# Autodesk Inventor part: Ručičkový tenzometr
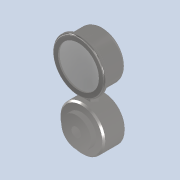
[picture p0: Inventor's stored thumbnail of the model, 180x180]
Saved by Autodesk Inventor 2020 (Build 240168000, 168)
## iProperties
Created: 2025-03
Part Number: Ručičkový tenzometr
Material: Hliník 6061
Document SubType Name: Modeling
Designer: doma
Density: 2.7 g/cm^3
Appearance: Hliník – plochý
Mass: 508.275 g
Surface Area: 271.618 cm^2
Volume: 188.25 cm^3
Author: doma
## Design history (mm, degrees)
sketch "Náčrt1"
  geometry: C1 r 30 at (0, 0); 1 further point
  constraints: 1 centre point, 1 coincident
  dimensions: "d0" = 60 diameter of C1
extrude "Vysunutí1" new body sketch "Náčrt1" stored distance "d1" = 30; taper "d2" = 0 deg
chamfer "Zkosení1" distance "d3" = 2; stored, may be unused: second distance "d4" = 2, angle "d5" = 45 deg
sketch "Náčrt2"
  geometry: C1 r 20 at (0, 0); 1 further point
  constraints: 1 centre point, 1 coincident
  dimensions: "d6" = 40 diameter of C1
extrude "Vysunutí2" join sketch "Náčrt2" distance "d7" = 7; taper "d8" = 0 deg
sketch "Náčrt3"
  geometry: C1 r 6.5 at (0, 0); 1 further point
  constraints: 1 centre point, 1 coincident
  dimensions: "d9" = 13 diameter of C1
extrude "Vysunutí3" cut sketch "Náčrt3" extent not by distance; stored distance "d10" = 0; taper "d11" = 0 deg
node "Pracovní rovina1"
sketch "Náčrt4"
  geometry: L1 (-4.041, -7)-(-8.083, 0); L2 (-8.083, 0)-(-4.041, 7); L3 (-4.041, 7)-(4.041, 7); L4 (4.041, 7)-(8.083, 0); L5 (8.083, 0)-(4.041, -7); L6 (4.041, -7)-(-4.041, -7); 2 further points
  constraints: 12 end point, 1 coincident, 13 other
  dimensions: "d13" = 14 distance between parallel lines of L3 L6
extrude "Vysunutí4" join sketch "Náčrt4" distance "d14" = 40; taper "d15" = 0 deg
sketch "Náčrt5"
  geometry: C1 r 31 at (0, 75); 1 further point
  constraints: 1 centre point
  dimensions: "d16" = 62 diameter of C1; "d17" = 75 distance of C1.centre point (0, 0)
extrude "Vysunutí5" join sketch "Náčrt5" stored distance "d18" = 28; taper "d19" = 0 deg
sketch "Náčrt6"
  geometry: C1 r 35 at (0, 0); 1 further point
  constraints: 1 centre point
  dimensions: "d20" = 70 diameter of C1
extrude "Vysunutí6" join sketch "Náčrt6" distance "d21" = 5; taper "d22" = 0 deg
fillet "Zaoblení2" dims "d24" = 2
fillet "Zaoblení3" dims "d25" = 1
sketch "Náčrt7"
  geometry: C1 r 27.5 at (0, 0); 1 further point
  constraints: 1 centre point
  dimensions: "d26" = 55 diameter of C1
extrude "Vysunutí7" cut sketch "Náčrt7" distance "d27" = 2; taper "d28" = 0 deg
fillet "Zaoblení4" dims "d29" = 5
node "Těleso1"
